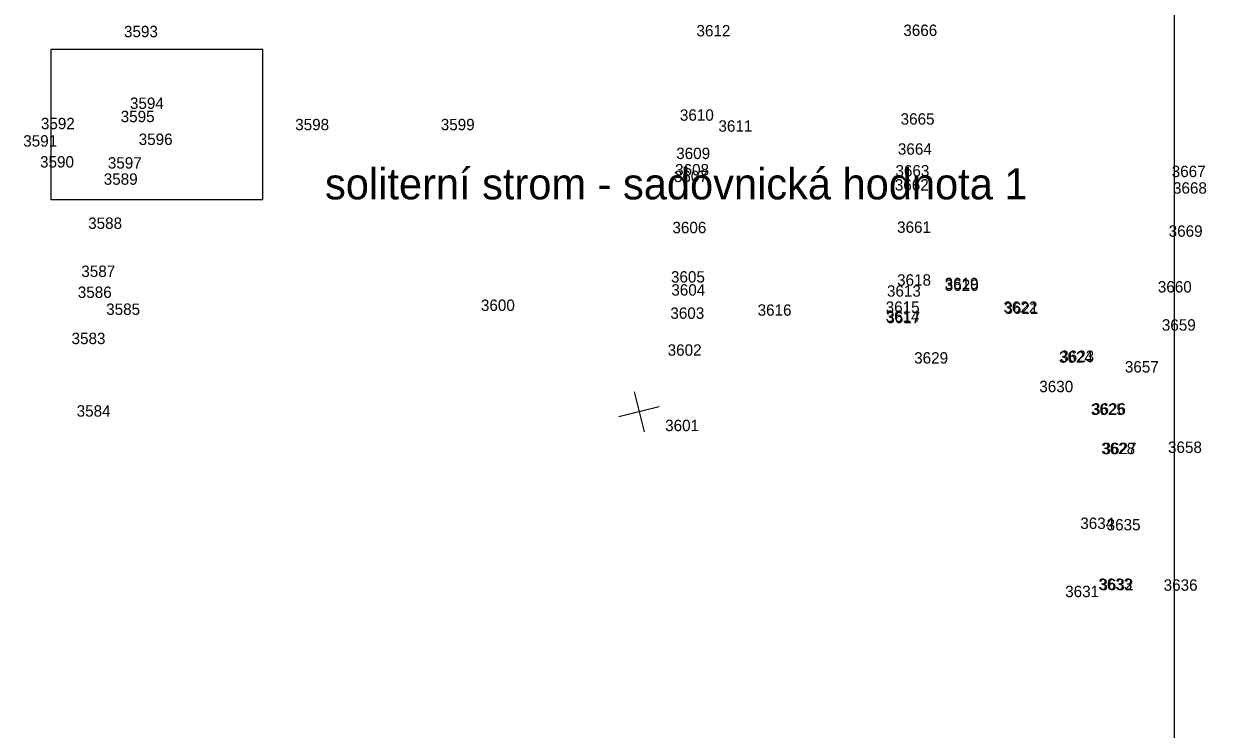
# Model space of a CAD drawing. Extents: x -740053 to -737517, y -1033516 to -1032488.
# Drawn here: x -739044.8 to -738987.3, y -1032590 to -1032556 of the extents above; entities that cross this region are included whole.
import ezdxf

# ---------------------------------------------------------------- set-up
doc = ezdxf.new("R2010")
doc.units = 0
for name, color, linetype in [('bod-cislo', 7, 'Continuous'), ('ctv-sit', 7, 'Continuous'), ('Predmety bez rozlišeni', 7, 'Continuous'), ('promika-formát', 7, 'Continuous')]:
    doc.layers.add(name, color=color, linetype=linetype)

# ---------------------------------------------------------------- blocks, each defined once
blk = doc.blocks.new('ctvsit')
for p, q in [((0, -2), (0, 2)), ((2, 0), (-2, 0))]:
    blk.add_line(p, q)

msp = doc.modelspace()

# ---------------------------------------------------------------- linework, layer by layer
at = {"layer": 'Predmety bez rozlišeni'}
msp.add_lwpolyline([(-739043.455, -1032564.478), (-739033.22, -1032564.478), (-739033.22, -1032557.244), (-739043.455, -1032557.244)], close=True, dxfattribs=at)
at = {"layer": 'promika-formát'}
msp.add_lwpolyline([(-738989.249, -1032654.978), (-738884.249, -1032654.978), (-738884.249, -1032506.478), (-738989.249, -1032506.478)], close=True, dxfattribs=at)

# ---------------------------------------------------------------- block references
at = {"layer": 'ctv-sit', "xscale": 0.49999999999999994, "yscale": 0.5, "rotation": 104.13020959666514}
msp.add_blockref('ctvsit', (-739015.067, -1032574.729), dxfattribs=at)

# ---------------------------------------------------------------- texts
at = {"layer": 'bod-cislo'}
for s, p in [('3593', (-739039.918, -1032556.653)), ('3612', (-739012.298, -1032556.613)), ('3666', (-739002.318, -1032556.593)), ('3594', (-739039.631, -1032560.113)), ('3610', (-739013.098, -1032560.683)), ('3592', (-739043.928, -1032561.093)), ('3595', (-739040.078, -1032560.753)), ('3598', (-739031.658, -1032561.143)), ('3599', (-739024.635, -1032561.143)), ('3611', (-739011.239, -1032561.213)), ('3665', (-739002.448, -1032560.873)), ('3591', (-739044.779, -1032561.933)), ('3596', (-739039.208, -1032561.853)), ('3664', (-739002.581, -1032562.323)), ('3590', (-739043.968, -1032562.943)), ('3597', (-739040.698, -1032562.993)), ('3609', (-739013.275, -1032562.533)), ('3608', (-739013.328, -1032563.323)), ('3663', (-739002.698, -1032563.373)), ('3667', (-738989.368, -1032563.403)), ('3589', (-739040.895, -1032563.773)), ('3607', (-739013.388, -1032563.643)), ('3662', (-739002.728, -1032564.053)), ('3668', (-738989.308, -1032564.203)), ('3588', (-739041.648, -1032565.903)), ('3606', (-739013.458, -1032566.113)), ('3661', (-739002.619, -1032566.093)), ('3669', (-738989.515, -1032566.283)), ('3587', (-739041.978, -1032568.223)), ('3605', (-739013.528, -1032568.493)), ('3618', (-739002.618, -1032568.643)), ('3586', (-739042.148, -1032569.233)), ('3604', (-739013.511, -1032569.123)), ('3613', (-739003.108, -1032569.173)), ('3619', (-739000.325, -1032568.813)), ('3620', (-739000.318, -1032568.893)), ('3660', (-738990.038, -1032568.973)), ('3600', (-739022.698, -1032569.863)), ('3585', (-739040.778, -1032570.053)), ('3603', (-739013.558, -1032570.243)), ('3616', (-739009.348, -1032570.093)), ('3614', (-739003.171, -1032570.393)), ('3615', (-739003.168, -1032569.953)), ('3617', (-739003.138, -1032570.453)), ('3622', (-738997.488, -1032569.953)), ('3621', (-738997.439, -1032570.003)), ('3659', (-738989.845, -1032570.813)), ('3583', (-739042.448, -1032571.463)), ('3602', (-739013.688, -1032572.023)), ('3629', (-739001.795, -1032572.403)), ('3624', (-738994.811, -1032572.363)), ('3623', (-738994.748, -1032572.323)), ('3657', (-738991.628, -1032572.833)), ('3630', (-738995.758, -1032573.783)), ('3584', (-739042.201, -1032574.963)), ('3625', (-738993.268, -1032574.883)), ('3626', (-738993.218, -1032574.863)), ('3601', (-739013.809, -1032575.663)), ('3628', (-738992.768, -1032576.773)), ('3627', (-738992.708, -1032576.773)), ('3658', (-738989.548, -1032576.713)), ('3634', (-738993.781, -1032580.383)), ('3635', (-738992.508, -1032580.453)), ('3631', (-738994.509, -1032583.673)), ('3633', (-738992.908, -1032583.323)), ('3632', (-738992.858, -1032583.343)), ('3636', (-738989.758, -1032583.363))]:
    msp.add_text(s, height=0.55, dxfattribs=at).set_placement(p)
at = {"layer": 'Predmety bez rozlišeni'}
msp.add_text('soliterní strom - sadovnická hodnota 1', height=1.5, rotation=360, dxfattribs=at).set_placement((-739030.22, -1032564.478))

doc.saveas('drawing.dxf')
